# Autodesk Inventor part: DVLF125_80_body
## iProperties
Created: 2010-04
Part Number: DVLF125_80_body
Document SubType Name: Modeling
Designer: TB
Mass: 3150.34 g
Surface Area: 3366.2 cm^2
Volume: 3150.34 cm^3
Density: 1 g/cm^3
Author: TB
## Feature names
1. Kropp [Revolution]
2. Chamfer
3. Extrusion2
4. Hole1
5. Revolution2
6. Hole2
7. Fillet1
8. Extrusion3
9. Hole3
